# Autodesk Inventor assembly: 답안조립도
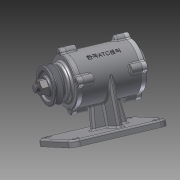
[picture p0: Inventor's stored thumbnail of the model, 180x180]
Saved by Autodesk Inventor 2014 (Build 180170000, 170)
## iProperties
Created: 2015-12
Part Number: 답안조립도
Document SubType Name: Assembly
Designer: test_25
Author: test_25
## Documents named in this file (11)
- C:\Users\test_25\Desktop\451207V1036\답안조립도.iam
- C:\Users\test_25\Desktop\451207V1036\V-벨트풀리.ipt
- C:\Users\test_25\Desktop\451207V1036\너트 M12x1.25.ipt
- C:\Users\test_25\Desktop\451207V1036\베어링 6204.ipt
- C:\Users\test_25\Desktop\451207V1036\본체.ipt
- C:\Users\test_25\Desktop\451207V1036\볼트 M4 x 12.ipt
- C:\Users\test_25\Desktop\451207V1036\오일실.ipt
- C:\Users\test_25\Desktop\451207V1036\축.ipt
- C:\Users\test_25\Desktop\451207V1036\커버.ipt
- C:\Users\test_25\Desktop\451207V1036\커버2.ipt
- C:\Users\test_25\Desktop\451207V1036\키(4 x 4 x 12).ipt
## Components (6 placed, 5 different names)
1. V-벨트풀리:1
2. KS B 1012 클래스 1 일반 - 미터 M12x1.25:1
3. KS B 2023 6204 - 20 x 47 x 14:1
4. KS B 2804 D D - 20 32 8:1
5. KS B 1311 (I) 4 x 4 x 12:1
6. KS B 2023 6204 - 20 x 47 x 14:2
